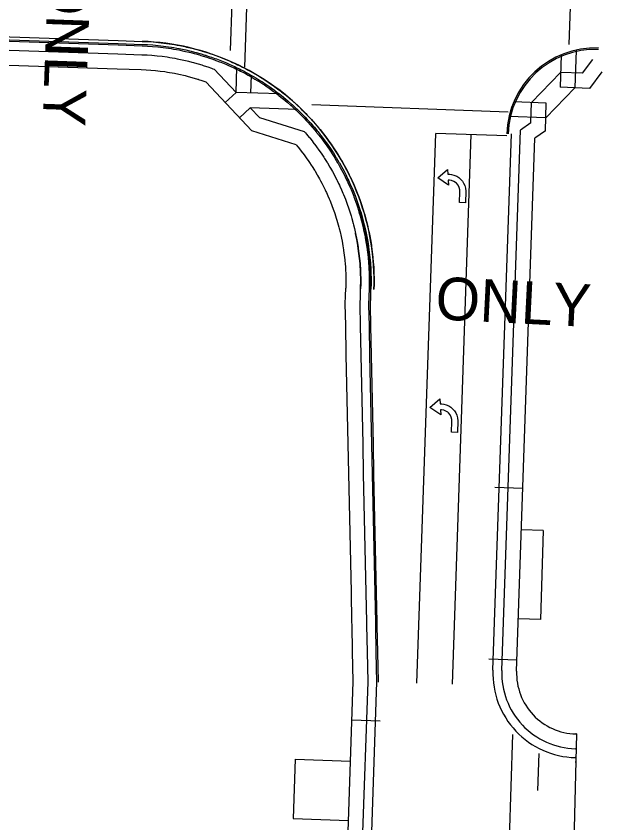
# Model space of a CAD drawing. Extents: x 979036 to 996074, y 1836928 to 1845163.
# Drawn here: x 992365.8 to 992563.5, y 1843635.7 to 1843908 of the extents above; entities that cross this region are included whole.
import ezdxf

# ---------------------------------------------------------------- set-up
doc = ezdxf.new("R2010")
doc.units = 0
for name, color, linetype in [('R_Proposed Road', 7, 'Continuous'), ('STRIPE_EXIST', 7, 'Continuous'), ('STRIPE_White Crosswalk', 7, 'Continuous'), ('STRIPE_White Stopbar', 7, 'Continuous'), ('STRIPE_White Turn Arrow', 7, 'Continuous'), ('STRIPE_White_6in', 7, 'Continuous'), ('STRIPE_White_ONLY', 7, 'Continuous'), ('STRIPE_Yellow Dbl 6in', 7, 'Continuous')]:
    doc.layers.add(name, color=color, linetype=linetype)

msp = doc.modelspace()

# ---------------------------------------------------------------- linework, layer by layer
at = {"layer": 'R_Proposed Road'}
for p, q in [((992549.79, 1843894.92), (992549.42, 1843883.92)), ((992554.85, 1843896.52), (992554.42, 1843883.75)), ((992560.29, 1843893.26), (992556.89, 1843888.67)), ((992432.64, 1843890.05), (992440.01, 1843882.17)), ((992440.01, 1843882.17), (992440.29, 1843890.58)), ((992445, 1843882), (992445.21, 1843888)), ((992549.59, 1843888.92), (992539.75, 1843878.78)), ((992556.89, 1843888.67), (992549.59, 1843888.92)), ((992563.51, 1843889.2), (992559.34, 1843883.58)), ((992429.8, 1843885.76), (992445.29, 1843869.19)), ((992559.34, 1843883.58), (992549.42, 1843883.92)), ((992440.01, 1843882.17), (992436.35, 1843878.76)), ((992454.67, 1843881.67), (992440.01, 1843882.17)), ((992544.58, 1843873.62), (992554.42, 1843883.75)), ((992544.75, 1843878.62), (992533.75, 1843878.99)), ((992539.52, 1843871.89), (992539.75, 1843878.78)), ((992544.43, 1843869.22), (992544.75, 1843878.62)), ((992444.83, 1843877), (992441.18, 1843873.59)), ((992444.83, 1843877), (992448.04, 1843873.57)), ((992460.73, 1843876.46), (992444.83, 1843877)), ((992463.15, 1843868.89), (992448.04, 1843873.57)), ((992544.58, 1843873.62), (992532.14, 1843874.04)), ((992539.52, 1843871.89), (992535.99, 1843869.43)), ((992460.3, 1843864.54), (992445.29, 1843869.19)), ((992526.74, 1843687.15), (992532.95, 1843868.2)), ((992529.74, 1843687.05), (992535.99, 1843869.43)), ((992544.43, 1843869.22), (992540.9, 1843866.76)), ((992534.74, 1843686.88), (992540.9, 1843866.76)), ((992536.85, 1843748.54), (992527.36, 1843748.87)), ((992543.73, 1843734.3), (992536.37, 1843734.55)), ((992543.73, 1843734.3), (992542.79, 1843704.31)), ((992542.79, 1843704.31), (992535.34, 1843704.57)), ((992534.86, 1843690.57), (992525.37, 1843690.9)), ((992471.17, 1843437.97), (992479.58, 1843683.42)), ((992476.08, 1843435.17), (992484.58, 1843683.25)), ((992479.19, 1843438.47), (992487.58, 1843683.15)), ((992479.14, 1843670.47), (992488.63, 1843670.15)), ((992554.9, 1843665.68), (992553.93, 1843626.83)), ((992554.9, 1843665.68), (992554.71, 1843665.68)), ((992554.77, 1843660.68), (992554.59, 1843660.68)), ((992459.98, 1843657.12), (992459.29, 1843637.13)), ((992459.98, 1843657.12), (992478.66, 1843656.48)), ((992554.66, 1843656.18), (992554.47, 1843656.19)), ((992554.7, 1843657.68), (992554.51, 1843657.69)), ((992459.29, 1843637.13), (992477.98, 1843636.49))]:
    msp.add_line(p, q, dxfattribs=at)
for points in [[(992360.2, 1843899.57), (992370.19, 1843899.23), (992380.18, 1843898.89), (992390.18, 1843898.55), (992400.17, 1843898.21), (992408.3, 1843897.93), (992410.08, 1843897.85), (992410.13, 1843897.85), (992411.86, 1843897.73), (992413.64, 1843897.57), (992415.41, 1843897.37), (992417.18, 1843897.13), (992418.12, 1843896.99), (992418.94, 1843896.85), (992419.91, 1843896.68), (992420.69, 1843896.53), (992422.44, 1843896.18), (992423, 1843896.05), (992424.18, 1843895.78), (992424.71, 1843895.65), (992425.91, 1843895.34), (992426.42, 1843895.2), (992427.63, 1843894.87), (992428.13, 1843894.72), (992429.34, 1843894.35), (992429.65, 1843894.25), (992429.83, 1843894.2), (992431.03, 1843893.8), (992431.52, 1843893.63), (992432.72, 1843893.21), (992433.21, 1843893.03), (992434.39, 1843892.58), (992434.89, 1843892.39), (992436.04, 1843891.92), (992436.57, 1843891.7), (992437.68, 1843891.22), (992438.23, 1843890.97), (992439.31, 1843890.48), (992439.34, 1843890.46), (992439.89, 1843890.2), (992440.92, 1843889.7), (992441.53, 1843889.39), (992442.5, 1843888.89), (992443.17, 1843888.54), (992444.08, 1843888.05), (992444.79, 1843887.65), (992445.63, 1843887.17), (992446.4, 1843886.71), (992447.16, 1843886.25), (992447.99, 1843885.73), (992448.67, 1843885.3), (992448.98, 1843885.1), (992449.57, 1843884.71), (992450.16, 1843884.32), (992451.14, 1843883.64), (992451.62, 1843883.3), (992452.68, 1843882.53), (992453.07, 1843882.25), (992454.21, 1843881.38), (992454.48, 1843881.17), (992455.72, 1843880.18), (992455.88, 1843880.06), (992457.22, 1843878.94), (992457.25, 1843878.92), (992458.55, 1843877.78), (992458.59, 1843877.74), (992458.69, 1843877.65), (992459.91, 1843876.54), (992460.14, 1843876.32), (992461.2, 1843875.3), (992461.57, 1843874.94), (992462.46, 1843874.04), (992462.97, 1843873.51), (992463.69, 1843872.75), (992464.36, 1843872.03), (992464.89, 1843871.43), (992465.72, 1843870.5), (992466.07, 1843870.09), (992467.05, 1843868.91), (992467.21, 1843868.72), (992468.02, 1843867.7), (992468.32, 1843867.33), (992468.36, 1843867.28), (992469.4, 1843865.91), (992469.64, 1843865.58), (992470.45, 1843864.46), (992470.89, 1843863.83), (992471.46, 1843863), (992472.12, 1843862.01), (992472.45, 1843861.51), (992473.31, 1843860.13), (992473.39, 1843860), (992474.31, 1843858.46), (992474.48, 1843858.17), (992475.19, 1843856.91), (992475.62, 1843856.13), (992476.03, 1843855.34), (992476.72, 1843854), (992476.84, 1843853.75), (992477.33, 1843852.74), (992477.62, 1843852.14), (992477.79, 1843851.77), (992478.35, 1843850.52), (992478.83, 1843849.42), (992479.05, 1843848.88), (992479.72, 1843847.22), (992479.83, 1843846.93), (992480.34, 1843845.55), (992480.79, 1843844.27), (992480.93, 1843843.87), (992481.48, 1843842.17), (992481.72, 1843841.4), (992481.99, 1843840.46), (992482.47, 1843838.74), (992482.6, 1843838.23), (992482.9, 1843837.01), (992483.3, 1843835.27), (992483.44, 1843834.62), (992483.66, 1843833.52), (992483.97, 1843831.77), (992484.21, 1843830.27), (992484.25, 1843830.01), (992484.49, 1843828.24), (992484.69, 1843826.47), (992484.85, 1843824.69), (992484.89, 1843824.08), (992484.97, 1843822.91), (992485.05, 1843821.13), (992485.09, 1843819.34), (992485.09, 1843817.56), (992485.05, 1843815.81)], [(992360.21, 1843900.07), (992370.21, 1843899.73), (992380.2, 1843899.39), (992390.2, 1843899.05), (992400.19, 1843898.71), (992408.31, 1843898.43), (992410.11, 1843898.35), (992410.16, 1843898.35), (992411.9, 1843898.23), (992413.69, 1843898.07), (992415.47, 1843897.87), (992417.25, 1843897.63), (992418.2, 1843897.48), (992419.02, 1843897.35), (992420, 1843897.17), (992420.79, 1843897.02), (992422.55, 1843896.66), (992423.11, 1843896.54), (992424.3, 1843896.26), (992424.83, 1843896.13), (992426.04, 1843895.82), (992426.55, 1843895.69), (992427.77, 1843895.35), (992428.27, 1843895.2), (992429.49, 1843894.83), (992429.8, 1843894.73), (992429.98, 1843894.67), (992431.19, 1843894.27), (992431.68, 1843894.11), (992432.89, 1843893.68), (992433.38, 1843893.5), (992434.57, 1843893.05), (992435.08, 1843892.85), (992436.24, 1843892.38), (992436.76, 1843892.16), (992437.89, 1843891.67), (992438.44, 1843891.43), (992439.52, 1843890.93), (992439.55, 1843890.92), (992440.1, 1843890.66), (992441.14, 1843890.15), (992441.76, 1843889.84), (992442.74, 1843889.34), (992443.4, 1843888.98), (992444.32, 1843888.49), (992445.04, 1843888.08), (992445.88, 1843887.6), (992446.66, 1843887.14), (992447.42, 1843886.68), (992448.26, 1843886.15), (992448.94, 1843885.72), (992449.25, 1843885.52), (992449.85, 1843885.13), (992450.44, 1843884.73), (992451.42, 1843884.05), (992451.91, 1843883.71), (992452.98, 1843882.94), (992453.36, 1843882.65), (992454.52, 1843881.78), (992454.79, 1843881.57), (992456.04, 1843880.57), (992456.19, 1843880.45), (992457.54, 1843879.32), (992457.57, 1843879.3), (992458.88, 1843878.15), (992458.92, 1843878.11), (992459.02, 1843878.03), (992460.25, 1843876.9), (992460.48, 1843876.68), (992461.55, 1843875.66), (992461.92, 1843875.29), (992462.81, 1843874.39), (992463.34, 1843873.85), (992464.05, 1843873.09), (992464.73, 1843872.36), (992465.27, 1843871.77), (992466.09, 1843870.82), (992466.45, 1843870.42), (992467.44, 1843869.23), (992467.6, 1843869.04), (992468.42, 1843868.01), (992468.71, 1843867.63), (992468.75, 1843867.58), (992469.8, 1843866.2), (992470.04, 1843865.88), (992470.86, 1843864.75), (992471.3, 1843864.11), (992471.88, 1843863.28), (992472.54, 1843862.28), (992472.87, 1843861.78), (992473.74, 1843860.39), (992473.82, 1843860.26), (992474.74, 1843858.71), (992474.91, 1843858.42), (992475.63, 1843857.15), (992476.06, 1843856.36), (992476.48, 1843855.57), (992477.17, 1843854.22), (992477.29, 1843853.97), (992477.79, 1843852.95), (992478.07, 1843852.35), (992478.24, 1843851.97), (992478.81, 1843850.72), (992479.29, 1843849.61), (992479.52, 1843849.07), (992480.18, 1843847.4), (992480.3, 1843847.11), (992480.81, 1843845.72), (992481.27, 1843844.43), (992481.4, 1843844.03), (992481.96, 1843842.32), (992482.2, 1843841.54), (992482.47, 1843840.6), (992482.95, 1843838.87), (992483.09, 1843838.35), (992483.39, 1843837.13), (992483.79, 1843835.38), (992483.93, 1843834.72), (992484.15, 1843833.62), (992484.47, 1843831.85), (992484.71, 1843830.34), (992484.75, 1843830.08), (992484.99, 1843828.3), (992485.19, 1843826.52), (992485.35, 1843824.73), (992485.39, 1843824.11), (992485.47, 1843822.94), (992485.55, 1843821.14), (992485.59, 1843819.35), (992485.59, 1843817.55), (992485.55, 1843815.79)], [(992360.09, 1843896.57), (992370.09, 1843896.23), (992380.08, 1843895.89), (992390.08, 1843895.55), (992400.07, 1843895.21), (992408.2, 1843894.94), (992409.91, 1843894.86), (992409.96, 1843894.86), (992411.62, 1843894.74), (992413.33, 1843894.59), (992415.04, 1843894.39), (992416.74, 1843894.16), (992417.65, 1843894.02), (992418.44, 1843893.89), (992419.37, 1843893.73), (992420.12, 1843893.59), (992421.81, 1843893.24), (992422.35, 1843893.12), (992423.48, 1843892.86), (992423.99, 1843892.74), (992425.14, 1843892.44), (992425.64, 1843892.31), (992426.8, 1843891.98), (992427.28, 1843891.84), (992428.44, 1843891.49), (992428.74, 1843891.4), (992428.91, 1843891.34), (992430.07, 1843890.96), (992430.54, 1843890.8), (992431.7, 1843890.39), (992432.17, 1843890.22), (992432.74, 1843890)], [(992359.92, 1843891.57), (992369.92, 1843891.23), (992379.91, 1843890.89), (992389.91, 1843890.55), (992399.9, 1843890.21), (992408.03, 1843889.94), (992409.63, 1843889.87), (992409.68, 1843889.86), (992411.23, 1843889.76), (992412.83, 1843889.61), (992414.42, 1843889.43), (992416.01, 1843889.22), (992416.86, 1843889.09), (992417.6, 1843888.97), (992418.47, 1843888.81), (992419.18, 1843888.68), (992420.75, 1843888.36), (992421.25, 1843888.25), (992422.31, 1843888), (992422.79, 1843887.88), (992423.87, 1843887.61), (992424.33, 1843887.48), (992425.41, 1843887.18), (992425.86, 1843887.05), (992426.95, 1843886.72), (992427.23, 1843886.63), (992427.39, 1843886.58), (992428.48, 1843886.22), (992429.8, 1843885.76)], [(992463.14, 1843868.88), (992463.45, 1843868.53), (992463.78, 1843868.14), (992464.73, 1843867.01), (992464.88, 1843866.83), (992465.67, 1843865.85), (992465.95, 1843865.48), (992465.99, 1843865.44), (992466.99, 1843864.12), (992467.22, 1843863.81), (992468, 1843862.73), (992468.43, 1843862.12), (992468.98, 1843861.32), (992469.61, 1843860.37), (992469.92, 1843859.88), (992470.76, 1843858.55), (992470.84, 1843858.43), (992471.72, 1843856.95), (992471.88, 1843856.67), (992472.56, 1843855.46), (992472.97, 1843854.71), (992473.37, 1843853.95), (992474.04, 1843852.66), (992474.15, 1843852.42), (992474.63, 1843851.44), (992474.9, 1843850.87), (992475.07, 1843850.51), (992475.61, 1843849.31), (992476.06, 1843848.25), (992476.28, 1843847.73), (992476.92, 1843846.14), (992477.03, 1843845.86), (992477.52, 1843844.53), (992477.96, 1843843.3), (992478.09, 1843842.91), (992478.62, 1843841.28), (992478.85, 1843840.53), (992479.11, 1843839.63), (992479.57, 1843837.98), (992479.7, 1843837.48), (992479.99, 1843836.31), (992480.37, 1843834.64), (992480.5, 1843834.01), (992480.71, 1843832.96), (992481.02, 1843831.27), (992481.25, 1843829.82), (992481.28, 1843829.57), (992481.51, 1843827.87), (992481.7, 1843826.16), (992481.86, 1843824.46), (992481.9, 1843823.87), (992481.97, 1843822.74), (992482.05, 1843821.03), (992482.09, 1843819.31), (992482.09, 1843817.59), (992482.05, 1843815.91)], [(992460.29, 1843864.53), (992460.87, 1843863.84), (992461.01, 1843863.67), (992461.74, 1843862.75), (992462.01, 1843862.41), (992462.98, 1843861.13), (992463.19, 1843860.84), (992463.92, 1843859.84), (992464.32, 1843859.27), (992464.83, 1843858.52), (992465.42, 1843857.63), (992465.72, 1843857.18), (992466.5, 1843855.93), (992466.57, 1843855.82), (992467.39, 1843854.44), (992467.55, 1843854.17), (992468.18, 1843853.04), (992468.57, 1843852.34), (992468.94, 1843851.63), (992469.56, 1843850.42), (992469.67, 1843850.2), (992470.12, 1843849.29), (992470.37, 1843848.76), (992470.53, 1843848.42), (992471.03, 1843847.29), (992471.46, 1843846.3), (992471.66, 1843845.82), (992472.26, 1843844.33), (992472.36, 1843844.07), (992472.82, 1843842.83), (992473.23, 1843841.68), (992473.35, 1843841.31), (992473.84, 1843839.79), (992474.06, 1843839.09), (992474.31, 1843838.25), (992474.73, 1843836.7), (992474.85, 1843836.24), (992475.12, 1843835.15), (992475.48, 1843833.58), (992475.6, 1843833), (992475.8, 1843832.01), (992476.09, 1843830.43), (992476.3, 1843829.08), (992476.34, 1843828.85), (992476.55, 1843827.26), (992476.73, 1843825.66), (992476.87, 1843824.07), (992476.91, 1843823.52), (992476.98, 1843822.46), (992477.05, 1843820.86), (992477.09, 1843819.26), (992477.09, 1843817.65), (992477.05, 1843816.08)], [(992487.58, 1843683.15), (992487.36, 1843693.27), (992487.17, 1843702.13), (992487.15, 1843703.28), (992486.94, 1843713.29), (992486.72, 1843723.31), (992486.51, 1843733.32), (992486.29, 1843743.33), (992486.08, 1843753.35), (992485.87, 1843763.36), (992485.65, 1843773.37), (992485.44, 1843783.39), (992485.23, 1843793.4), (992485.01, 1843803.41), (992484.86, 1843810.42), (992484.96, 1843813.42), (992485.04, 1843815.78), (992485.08, 1843817.32), (992485.09, 1843817.56), (992485.09, 1843819.34), (992485.05, 1843821.13), (992484.97, 1843822.91), (992484.95, 1843823.28), (992484.85, 1843824.69), (992484.69, 1843826.47), (992484.49, 1843828.24), (992484.25, 1843830.01), (992483.97, 1843831.77), (992483.73, 1843833.14), (992483.66, 1843833.52), (992483.3, 1843835.27), (992482.9, 1843837.01), (992482.47, 1843838.74), (992481.99, 1843840.46), (992481.62, 1843841.7)], [(992488.08, 1843683.16), (992488.08, 1843683.24), (992487.86, 1843693.25), (992487.67, 1843702.11), (992487.65, 1843703.26), (992487.44, 1843713.28), (992487.22, 1843723.29), (992487.01, 1843733.3), (992486.79, 1843743.32), (992486.58, 1843753.33), (992486.37, 1843763.34), (992486.15, 1843773.35), (992485.94, 1843783.37), (992485.72, 1843793.38), (992485.51, 1843803.39), (992485.36, 1843810.4), (992485.46, 1843813.4), (992485.54, 1843815.76), (992485.58, 1843817.32), (992485.59, 1843817.55), (992485.59, 1843819.35), (992485.55, 1843821.14), (992485.47, 1843822.94), (992485.45, 1843823.31), (992485.35, 1843824.73), (992485.19, 1843826.52), (992484.99, 1843828.3), (992484.75, 1843830.08), (992484.47, 1843831.85), (992484.22, 1843833.24), (992484.15, 1843833.62), (992483.79, 1843835.38), (992483.39, 1843837.13), (992482.95, 1843838.87), (992482.47, 1843840.6), (992481.96, 1843842.32), (992481.81, 1843842.78)], [(992484.58, 1843683.25), (992484.37, 1843693.37), (992484.18, 1843702.23), (992484.15, 1843703.38), (992483.94, 1843713.4), (992483.72, 1843723.41), (992483.51, 1843733.42), (992483.3, 1843743.43), (992483.08, 1843753.45), (992482.87, 1843763.46), (992482.65, 1843773.47), (992482.44, 1843783.49), (992482.23, 1843793.5), (992482.01, 1843803.51), (992481.86, 1843810.52), (992481.97, 1843813.52), (992482.05, 1843815.88), (992482.08, 1843817.37), (992482.09, 1843817.59), (992482.09, 1843819.31), (992482.05, 1843821.03), (992481.97, 1843822.74), (992481.95, 1843823.1), (992481.86, 1843824.46), (992481.7, 1843826.16), (992481.51, 1843827.87), (992481.28, 1843829.57), (992481.02, 1843831.27), (992480.78, 1843832.59), (992480.71, 1843832.96), (992480.37, 1843834.64), (992480.36, 1843834.65)], [(992479.58, 1843683.42), (992479.37, 1843693.54), (992479.18, 1843702.4), (992479.15, 1843703.55), (992478.94, 1843713.57), (992478.73, 1843723.58), (992478.51, 1843733.59), (992478.3, 1843743.61), (992478.09, 1843753.62), (992477.87, 1843763.63), (992477.66, 1843773.65), (992477.44, 1843783.66), (992477.23, 1843793.67), (992477.02, 1843803.68), (992476.87, 1843810.69), (992476.97, 1843813.69), (992477.05, 1843816.05), (992477.05, 1843816.08)]]:
    msp.add_lwpolyline(points, dxfattribs=at)
for centre, radius, start, end in [((992405.6, 1843818.49), 81, 358.0437, 88.0557), ((992561.36, 1843867.23), 30, 88.0557, 178.0437), ((992561.36, 1843867.23), 29.5, 88.0557, 178.0437), ((992555.22, 1843686.18), 28.5, 178.0361, 268.5687), ((992555.22, 1843686.18), 25.5, 178.0361, 268.5687), ((992555.22, 1843686.18), 20.5, 178.0361, 268.5687)]:
    msp.add_arc(centre, radius, start, end, dxfattribs=at)
at = {"layer": 'STRIPE_EXIST'}
for p, q in [((992444.51, 1843940.63), (992442.87, 1843890.72)), ((992553.36, 1843927.31), (992552.41, 1843898.33)), ((992438.57, 1843912.31), (992438.05, 1843896.32))]:
    msp.add_line(p, q, dxfattribs=at)
msp.add_lwpolyline([(992360.25, 1843901.08), (992370.24, 1843900.74), (992380.24, 1843900.4), (992390.23, 1843900.06), (992400.22, 1843899.72), (992408.35, 1843899.44), (992410.16, 1843899.36), (992410.22, 1843899.36), (992411.98, 1843899.24), (992413.79, 1843899.07), (992415.6, 1843898.87), (992417.4, 1843898.63), (992418.36, 1843898.48), (992419.19, 1843898.34), (992420.18, 1843898.17), (992420.98, 1843898.02), (992422.76, 1843897.65), (992423.33, 1843897.52), (992424.53, 1843897.25), (992425.08, 1843897.11), (992426.3, 1843896.8), (992426.82, 1843896.66), (992428.05, 1843896.32), (992428.55, 1843896.17), (992429.79, 1843895.79), (992430.1, 1843895.69), (992430.29, 1843895.64), (992431.52, 1843895.23), (992432.01, 1843895.06), (992433.23, 1843894.63), (992433.73, 1843894.45), (992434.94, 1843893.99), (992435.45, 1843893.79), (992436.62, 1843893.31), (992437.15, 1843893.09), (992438.29, 1843892.6), (992438.85, 1843892.35), (992439.95, 1843891.85), (992439.98, 1843891.83), (992440.54, 1843891.57), (992441.59, 1843891.06), (992442.22, 1843890.74), (992443.21, 1843890.23), (992443.88, 1843889.87), (992444.81, 1843889.37), (992445.53, 1843888.96), (992446.39, 1843888.47), (992447.17, 1843888.01), (992447.95, 1843887.54), (992448.8, 1843887.01), (992449.49, 1843886.57), (992449.8, 1843886.37), (992450.41, 1843885.97), (992451, 1843885.57), (992452, 1843884.88), (992452.5, 1843884.53), (992453.58, 1843883.75), (992453.97, 1843883.46), (992455.14, 1843882.58), (992455.41, 1843882.36), (992456.68, 1843881.36), (992456.83, 1843881.23), (992458.2, 1843880.09), (992458.23, 1843880.06), (992459.55, 1843878.91), (992459.6, 1843878.87), (992459.7, 1843878.78), (992460.94, 1843877.64), (992461.17, 1843877.42), (992462.25, 1843876.38), (992462.63, 1843876.01), (992463.54, 1843875.1), (992464.06, 1843874.55), (992464.79, 1843873.78), (992465.47, 1843873.04), (992466.02, 1843872.44), (992466.86, 1843871.49), (992467.21, 1843871.07), (992468.22, 1843869.87), (992468.38, 1843869.68), (992469.21, 1843868.64), (992469.51, 1843868.25), (992469.55, 1843868.2), (992470.61, 1843866.81), (992470.86, 1843866.48), (992471.68, 1843865.34), (992472.13, 1843864.69), (992472.71, 1843863.84), (992473.38, 1843862.84), (992473.72, 1843862.32), (992474.6, 1843860.92), (992474.68, 1843860.78), (992475.61, 1843859.22), (992475.79, 1843858.92), (992476.51, 1843857.64), (992476.95, 1843856.84), (992477.37, 1843856.04), (992478.07, 1843854.67), (992478.2, 1843854.42), (992478.7, 1843853.39), (992478.98, 1843852.78), (992479.16, 1843852.4), (992479.73, 1843851.13), (992480.22, 1843850), (992480.45, 1843849.45), (992481.12, 1843847.77), (992481.24, 1843847.47), (992481.76, 1843846.07), (992482.22, 1843844.76), (992482.36, 1843844.35), (992482.92, 1843842.62), (992483.16, 1843841.83), (992483.45, 1843840.88), (992483.93, 1843839.13), (992484.06, 1843838.6), (992484.37, 1843837.36), (992484.78, 1843835.59), (992484.92, 1843834.93), (992485.14, 1843833.81), (992485.46, 1843832.02), (992485.71, 1843830.49), (992485.75, 1843830.23), (992485.99, 1843828.42), (992486.19, 1843826.62), (992486.35, 1843824.81), (992486.4, 1843824.18), (992486.48, 1843822.99), (992486.56, 1843821.18), (992486.6, 1843819.36), (992486.6, 1843817.54), (992486.55, 1843815.76)], dxfattribs=at)
at = {"layer": 'STRIPE_White Crosswalk'}
for p, q in [((992465.65, 1843878.13), (992531.87, 1843875.63)), ((992532.3, 1843630.35), (992533.5, 1843665.48))]:
    msp.add_line(p, q, dxfattribs=at)
at = {"layer": 'STRIPE_White Stopbar'}
for p, q in [((992531.43, 1843867.56), (992507.44, 1843868.37)), ((992541.86, 1843646.57), (992542.29, 1843659.11))]:
    msp.add_line(p, q, dxfattribs=at)
at = {"layer": 'STRIPE_White Turn Arrow'}
for points in [[(992511.77, 1843850.92), (992508.16, 1843853.36), (992511.43, 1843856.24), (992511.54, 1843854.57), (992512.21, 1843854.56), (992512.78, 1843854.5), (992513.58, 1843854.31), (992514.5, 1843853.91), (992515.22, 1843853.48), (992515.8, 1843852.91), (992516.47, 1843852.26), (992516.85, 1843851.56), (992517.26, 1843850.8), (992517.49, 1843849.85), (992517.62, 1843848.86), (992517.43, 1843844.97), (992515.42, 1843845.06), (992515.56, 1843848.65), (992515.54, 1843849.34), (992515.34, 1843850.08), (992514.99, 1843850.87), (992514.44, 1843851.53), (992514.15, 1843851.76), (992513.54, 1843852.15), (992512.79, 1843852.42), (992512.06, 1843852.56), (992511.67, 1843852.58)], [(992509.1, 1843773.41), (992505.48, 1843775.85), (992508.76, 1843778.73), (992508.87, 1843777.06), (992509.53, 1843777.05), (992510.11, 1843776.99), (992510.9, 1843776.8), (992511.83, 1843776.41), (992512.55, 1843775.97), (992513.13, 1843775.4), (992513.8, 1843774.75), (992514.17, 1843774.05), (992514.58, 1843773.29), (992514.82, 1843772.34), (992514.94, 1843771.36), (992514.75, 1843767.46), (992512.75, 1843767.55), (992512.89, 1843771.14), (992512.87, 1843771.83), (992512.67, 1843772.57), (992512.32, 1843773.36), (992511.77, 1843774.02), (992511.47, 1843774.25), (992510.87, 1843774.64), (992510.12, 1843774.91), (992509.39, 1843775.05), (992509, 1843775.07)]]:
    msp.add_lwpolyline(points, close=True, dxfattribs=at)
at = {"layer": 'STRIPE_White_6in'}
msp.add_line((992513.07, 1843682.45), (992519.43, 1843867.97), dxfattribs=at)
at = {"layer": 'STRIPE_Yellow Dbl 6in'}
msp.add_line((992501.08, 1843682.87), (992507.44, 1843868.38), dxfattribs=at)

# ---------------------------------------------------------------- texts
at = {"layer": 'STRIPE_EXIST'}
msp.add_text('ONLY', height=14.4, rotation=267.9663, dxfattribs=at).set_placement((992376.56, 1843923.46))
at = {"layer": 'STRIPE_White_ONLY'}
msp.add_text('ONLY', height=14.4, rotation=357.1266, dxfattribs=at).set_placement((992507.1, 1843805.64))

doc.saveas('drawing.dxf')
